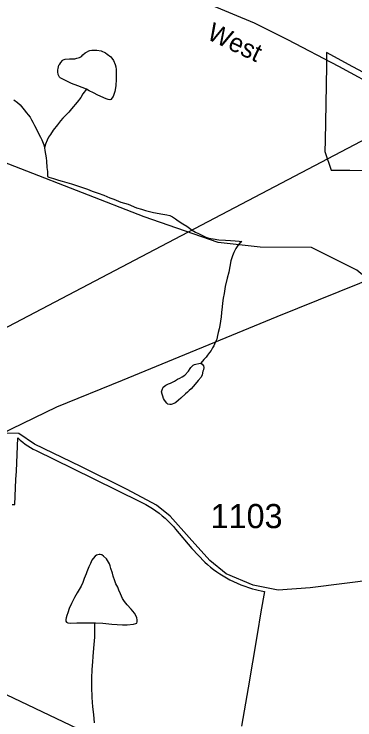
# Model space of a CAD drawing. Extents: x 2001466 to 2224147, y 644118 to 847247.
# Drawn here: x 2050483 to 2052246, y 663505 to 667157 of the extents above; entities that cross this region are included whole.
import ezdxf

# ---------------------------------------------------------------- set-up
doc = ezdxf.new("R2010")
doc.units = 0
for name, color, linetype in [('Exist Boundary Political City Limit New', 7, 'Continuous'), ('Exist Hydrographic Creek Single Shore', 7, 'Continuous'), ('Exist Hydrographic Misc Water Feature', 7, 'Continuous'), ('Exist Railroad Mainline', 7, 'Continuous'), ('Exist Road Primary NC Attributed', 7, 'Continuous'), ('Exist Road Secondary Type 51 Attributed', 7, 'Continuous'), ('Exist Road Secondary Type 51 Label', 7, 'Continuous'), ('Exist Road Secondary Type 51 Number Label', 7, 'Continuous'), ('Exist Utilities Electrical Transmission Line', 7, 'Continuous'), ('Map Preparation Boundary City Limit Buffer Line', 7, 'Continuous')]:
    doc.layers.add(name, color=color, linetype=linetype)

msp = doc.modelspace()

# ---------------------------------------------------------------- linework, layer by layer
at = {"layer": 'Exist Boundary Political City Limit New'}
for points in [[(2054801.8, 667751.5), (2053660.4, 667152.6), (2053327.5, 666977.9), (2052690.6, 666643.7), (2052574.2, 666699.1), (2052338.9, 666828.2), (2052265, 666867.9), (2052235.1, 666884), (2052099.1, 666957.6), (2052098.8, 666888.7), (2052095.1, 666691.8)], [(2052095.1, 666691.8), (2052092, 666502.8), (2052090.8, 666445.9), (2052123.5, 666350), (2052220.5, 666348.5), (2052394.6, 666345.8), (2052718.4, 666340.8), (2052814, 666339.7), (2052993.8, 666337.4), (2053061.5, 666128.9), (2053171.9, 666173.9), (2053238.5, 665962.8), (2053447.8, 666053.3), (2053459.1, 666013.7), (2054053.1, 666251.2), (2054374.5, 666381.3), (2054368.9, 666466.1), (2054832.8, 666624.4), (2055228.8, 666788.4), (2055490.1, 666895.9), (2055727.8, 666155.1)], [(2050474, 664618.4), (2050486.8, 664618.5), (2050493, 664748.4), (2050495, 664791.6), (2050503, 664963.4), (2050515.1, 664952.3), (2050527.8, 664941.8), (2050540.8, 664931.8), (2050554.2, 664922.4), (2050568.1, 664913.6), (2050582.4, 664905.4), (2050597, 664897.9), (2050787.6, 664804.9), (2050895.5, 664751.6), (2051136.9, 664633.8), (2051164.9, 664619.1), (2051182.5, 664608.8), (2051199.8, 664597.9), (2051216.5, 664586.4), (2051232.9, 664574.2), (2051248.8, 664561.4), (2051264.1, 664548.1), (2051279, 664534.2), (2051293.4, 664519.8), (2051307.2, 664504.8), (2051318.5, 664491.8), (2051403, 664392.1), (2051469.1, 664321.4), (2051484.1, 664308.1), (2051499.5, 664295.4), (2051515.2, 664283.1), (2051531.5, 664271.4), (2051548, 664260.1), (2051564.9, 664249.5), (2051582.1, 664239.4), (2051599.8, 664229.8), (2051617.6, 664220.8), (2051636.9, 664211.9), (2051656.5, 664203.7), (2051676.4, 664196.2), (2051696.6, 664189.3), (2051717, 664183.2), (2051731.4, 664179.2), (2051745.9, 664175.7), (2051760.6, 664172.5), (2051778, 664169.2), (2051760.1, 664063.8), (2051740.4, 663946.6), (2051716.2, 663803.9), (2051693.8, 663670.6), (2051660.2, 663472.7)]]:
    msp.add_lwpolyline(points, dxfattribs=at)
at = {"layer": 'Exist Hydrographic Creek Single Shore'}
msp.add_lwpolyline([(2053273.2, 665427.7), (2053006.3, 665420.1), (2052782.4, 665359), (2052490.4, 665574.9), (2052414.3, 665701.1), (2052256.4, 665832.3), (2052022.2, 665948.5), (2051756.3, 665950.7), (2051539.3, 665974.8), (2051155.3, 666107.3), (2050197.3, 666481), (2049997.3, 666488.4), (2049843.6, 666575.6)], dxfattribs=at)
at = {"layer": 'Exist Hydrographic Misc Water Feature'}
for points in [[(2050857.7, 666768), (2050813.6, 666786), (2050779.6, 666797.9), (2050739.6, 666817.7), (2050721.6, 666827.8), (2050717.7, 666829.8), (2050711.5, 666843.7), (2050709.7, 666857.7), (2050709.5, 666867.7), (2050711.5, 666875.7), (2050715.4, 666891.7), (2050719.5, 666897.8), (2050725.5, 666905.8), (2050733.5, 666915.8), (2050737.4, 666919.8), (2050741.5, 666921.8), (2050747.4, 666923.8), (2050769.4, 666925.8), (2050787.4, 666925.8), (2050797.2, 666925.9), (2050807.3, 666927.9), (2050821.4, 666931.9), (2050831.3, 666938), (2050839.3, 666945.9), (2050851.4, 666955.9), (2050857.3, 666959.9), (2050869.4, 666966), (2050875.4, 666968), (2050885.4, 666970), (2050911.3, 666970.1), (2050933.4, 666966.1), (2050955.3, 666956.1), (2050965.4, 666950.2), (2050983.4, 666936.2), (2050989.4, 666928.2), (2050997.4, 666916.3), (2051005.4, 666896.3), (2051009.5, 666884.3), (2051011.5, 666870.3), (2051011.5, 666852.3), (2051011.5, 666820.3), (2051009.7, 666786.3), (2051003.7, 666756.3), (2050995.7, 666730.3), (2050983.6, 666714.3), (2050977.7, 666712.3), (2050969.7, 666714.2), (2050959.6, 666718.2), (2050915.8, 666738.1), (2050893.6, 666750.1), (2050871.7, 666760), (2050857.7, 666768)], [(2050857.7, 666768), (2050839.7, 666744), (2050827.8, 666725.9), (2050809.8, 666701.9), (2050779.8, 666665.9), (2050765.9, 666649.9), (2050754, 666637.8), (2050735.9, 666617.8), (2050724, 666603.8), (2050708, 666583.8), (2050686.1, 666555.8), (2050672.2, 666533.7), (2050662.1, 666519.7), (2050654.1, 666503.7), (2050646.1, 666483.7), (2050640.2, 666465.6)], [(2050481.9, 666713.3), (2050501.8, 666699.4), (2050513.9, 666687.4), (2050536, 666661.4), (2050547.9, 666645.4), (2050555.9, 666635.4), (2050565.9, 666623.5), (2050573.9, 666609.5), (2050580.1, 666597.5), (2050588.1, 666579.6), (2050596.1, 666567.6), (2050610, 666539.6), (2050620.3, 666519.6), (2050626.2, 666505.6), (2050636.3, 666479.7), (2050640.2, 666465.6)], [(2050640.2, 666465.6), (2050642.2, 666451.7), (2050646.3, 666431.7), (2050648.4, 666413.7), (2050650.4, 666395.7), (2050652.5, 666363.7), (2050656.4, 666341.7), (2050656.6, 666315.7)], [(2050656.6, 666315.7), (2050662.5, 666313.8), (2050686.5, 666305.8), (2050712.6, 666297.8), (2050732.7, 666291.9), (2050780.6, 666277.9), (2050836.6, 666260.1), (2050862.7, 666250.2), (2050886.6, 666240.2), (2050918.6, 666230.2), (2050946.7, 666220.3), (2050978.7, 666206.3), (2050998.6, 666198.4), (2051034.7, 666184.4), (2051072.6, 666172.5), (2051116.7, 666154.6), (2051142.8, 666146.7), (2051162.6, 666140.7), (2051204.9, 666130.8), (2051252.9, 666120.9), (2051272.8, 666118.9), (2051288.8, 666115), (2051302.9, 666107), (2051318.9, 666097), (2051332.8, 666087), (2051356.8, 666071.1), (2051376.7, 666059.1), (2051390.9, 666049.2), (2051405, 666039.2), (2051421, 666029.2), (2051437, 666021.2), (2051474.9, 666003.3), (2051490.9, 665997.3), (2051512.9, 665993.4), (2051543, 665989.5), (2051576.9, 665987.5), (2051602.9, 665985.5), (2051626.9, 665983.6), (2051647, 665981.6), (2051660.9, 665979.6)], [(2051660.9, 665979.6), (2051650.9, 665971.6), (2051640.8, 665959.6), (2051631, 665943.6), (2051619.1, 665923.6), (2051613.1, 665905.6), (2051605.1, 665879.6), (2051599.2, 665851.6), (2051593.3, 665821.6), (2051585.3, 665789.6), (2051575.4, 665747.5), (2051569.5, 665711.5), (2051565.6, 665687.5), (2051561.5, 665661.6), (2051559.6, 665641.5), (2051555.7, 665613.5), (2051553.7, 665589.5), (2051551.6, 665567.5), (2051547.7, 665545.5), (2051543.8, 665527.6), (2051539.7, 665509.6), (2051535.8, 665493.5), (2051531.9, 665475.5), (2051523.9, 665457.5), (2051516, 665439.5), (2051510, 665429.5), (2051502, 665415.5), (2051494, 665405.5), (2051484, 665391.4), (2051476, 665381.4), (2051464.1, 665369.4), (2051449.7, 665351.4)], [(2051449.7, 665351.4), (2051456.1, 665345.4), (2051462.2, 665337.4), (2051464.1, 665327.4), (2051462.2, 665315.4), (2051460.2, 665309.4), (2051456.3, 665289.4), (2051450.3, 665277.4), (2051436.2, 665261.4), (2051420.2, 665241.3), (2051398.5, 665217.4), (2051388.4, 665209.3), (2051380.4, 665201.3), (2051370.4, 665191.3), (2051346.6, 665169.2), (2051334.5, 665159.2), (2051320.5, 665147.2), (2051314.6, 665143.1), (2051296.5, 665137.1), (2051288.5, 665137.1), (2051278.5, 665139.1), (2051272.6, 665143.1), (2051260.5, 665159.1), (2051256.6, 665167.1), (2051252.5, 665179), (2051248.4, 665191), (2051246.3, 665203), (2051248.4, 665213), (2051254.5, 665227), (2051268.5, 665237.1), (2051282.4, 665243.1), (2051292.2, 665247.1), (2051312.3, 665257.1), (2051328.3, 665267.1), (2051340.2, 665273.2), (2051352.3, 665279.2), (2051366.3, 665289.2), (2051386.2, 665309.3), (2051394.2, 665323.3), (2051398.3, 665327.3), (2051404.2, 665335.3), (2051410.1, 665339.4), (2051416.1, 665343.4), (2051424.1, 665345.4), (2051438.2, 665349.4), (2051449.7, 665351.4)], [(2050898.5, 664006.6), (2050904.7, 664006.6), (2050942.6, 664004.7), (2050988.6, 664000.8), (2051016.6, 663998.8), (2051044.5, 663996.9), (2051068.5, 663996.9), (2051100.7, 664000.9), (2051112.6, 664003), (2051118.6, 664005), (2051120.6, 664013), (2051120.6, 664021), (2051118.6, 664035), (2051106.5, 664057), (2051088.4, 664077), (2051068.5, 664100.9), (2051054.6, 664116.9), (2051044.3, 664132.8), (2051034.3, 664156.8), (2051024.4, 664176.8), (2051020.3, 664190.8), (2051010.3, 664208.8), (2051004.3, 664224.8), (2050996.3, 664248.8), (2050992, 664264.7), (2050984, 664288.7), (2050980.2, 664302.7), (2050976, 664312.7), (2050962.1, 664338.7), (2050946.1, 664352.7), (2050937.9, 664358.7), (2050928.1, 664360.6), (2050924, 664360.6), (2050910, 664356.6), (2050902, 664352.6), (2050892, 664340.5), (2050886.2, 664330.5), (2050878, 664314.5), (2050870, 664296.5), (2050860.2, 664270.5), (2050856.3, 664260.4), (2050846.3, 664236.4), (2050838.3, 664216.4), (2050830.5, 664196.5), (2050810.4, 664162.4), (2050796.4, 664138.4), (2050780.4, 664106.4), (2050768.5, 664080.3), (2050760.5, 664058.4), (2050756.6, 664044.3), (2050752.5, 664032.3), (2050750.7, 664024.3), (2050750.7, 664016.3), (2050754.8, 664010.3), (2050760.7, 664006.3), (2050774.7, 664004.4), (2050808.7, 664006.5), (2050836.6, 664006.5), (2050878.6, 664006.6), (2050898.5, 664006.6)], [(2050898.5, 664006.6), (2050898.7, 663968.6), (2050898.7, 663932.7), (2050894.8, 663876.6), (2050891, 663832.6), (2050888.9, 663804.7), (2050885.2, 663764.7), (2050883.2, 663720.6), (2050883.2, 663676.6), (2050885.4, 663620.7), (2050889.5, 663572.6), (2050893.4, 663532.7), (2050897.5, 663488.7)]]:
    msp.add_lwpolyline(points, dxfattribs=at)
at = {"layer": 'Exist Railroad Mainline'}
msp.add_lwpolyline([(2046464.5, 663426.2), (2046524.6, 663459.1), (2048551.7, 664535.4), (2049194.6, 664876.7), (2049524.4, 665051.8), (2049557.2, 665070.3), (2052622.8, 666680.7), (2055671.2, 668278.9), (2056997.6, 668963.3), (2058840.6, 669936.5)], dxfattribs=at)
at = {"layer": 'Exist Road Primary NC Attributed'}
msp.add_lwpolyline([(2050426, 664989), (2050469.1, 665011), (2050704.3, 665125.3), (2051044.1, 665262.3), (2051844.1, 665591.2), (2052698.6, 665937.8), (2053399.3, 666214.3), (2053976.4, 666455.2), (2054260.6, 666569.3)], dxfattribs=at)
at = {"layer": 'Exist Road Secondary Type 51 Attributed'}
for points in [[(2052557.1, 666646.2), (2052386.3, 666764), (2052162.5, 666885.4), (2051899.2, 667023.8), (2051726.1, 667110.4), (2051482.2, 667211.8), (2051238.9, 667288.9), (2050792.4, 667405.1), (2050170.2, 667573.1), (2049959.6, 667625.9), (2049883.6, 667635.4), (2049783.3, 667640.7), (2049542.6, 667618.5), (2049242.3, 667606.9)], [(2052683.1, 664272.6), (2052013.9, 664187.6), (2051850, 664175.9), (2051719.6, 664202.3), (2051580.5, 664260.9), (2051495.8, 664330.1), (2051388.7, 664448.4), (2051289.9, 664559.7), (2051219.6, 664615.4), (2051068.8, 664697.4), (2050828.7, 664816.1), (2050588.7, 664932.1), (2050508.7, 664986), (2050426, 664989)]]:
    msp.add_lwpolyline(points, dxfattribs=at)
at = {"layer": 'Exist Utilities Electrical Transmission Line'}
msp.add_lwpolyline([(2063583.7, 657590.1), (2059873.3, 658420.5), (2058009.5, 660180.5), (2056432.8, 660774), (2050997.3, 663369.7), (2049560.3, 664054.6)], dxfattribs=at)
at = {"layer": 'Map Preparation Boundary City Limit Buffer Line'}
for points in [[(2054801.8, 667751.5), (2053660.4, 667152.6), (2053327.5, 666977.9), (2052690.6, 666643.7), (2052574.2, 666699.1), (2052338.9, 666828.2), (2052265, 666867.9), (2052235.1, 666884), (2052099.1, 666957.6), (2052098.8, 666888.7), (2052095.1, 666691.8)], [(2052095.1, 666691.8), (2052092, 666502.8), (2052090.8, 666445.9), (2052123.5, 666350), (2052220.5, 666348.5), (2052394.6, 666345.8), (2052718.4, 666340.8), (2052814, 666339.7), (2052993.8, 666337.4), (2053061.5, 666128.9), (2053171.9, 666173.9), (2053238.5, 665962.8), (2053447.8, 666053.3), (2053459.1, 666013.7), (2054053.1, 666251.2), (2054374.5, 666381.3), (2054368.9, 666466.1), (2054832.8, 666624.4), (2055228.8, 666788.4), (2055490.1, 666895.9), (2055727.8, 666155.1)], [(2050474, 664618.4), (2050486.8, 664618.5), (2050493, 664748.4), (2050495, 664791.6), (2050503, 664963.4), (2050515.1, 664952.3), (2050527.8, 664941.8), (2050540.8, 664931.8), (2050554.2, 664922.4), (2050568.1, 664913.6), (2050582.4, 664905.4), (2050597, 664897.9), (2050787.6, 664804.9), (2050895.5, 664751.6), (2051136.9, 664633.8), (2051164.9, 664619.1), (2051182.5, 664608.8), (2051199.8, 664597.9), (2051216.5, 664586.4), (2051232.9, 664574.2), (2051248.8, 664561.4), (2051264.1, 664548.1), (2051279, 664534.2), (2051293.4, 664519.8), (2051307.2, 664504.8), (2051318.5, 664491.8), (2051403, 664392.1), (2051469.1, 664321.4), (2051484.1, 664308.1), (2051499.5, 664295.4), (2051515.2, 664283.1), (2051531.5, 664271.4), (2051548, 664260.1), (2051564.9, 664249.5), (2051582.1, 664239.4), (2051599.8, 664229.8), (2051617.6, 664220.8), (2051636.9, 664211.9), (2051656.5, 664203.7), (2051676.4, 664196.2), (2051696.6, 664189.3), (2051717, 664183.2), (2051731.4, 664179.2), (2051745.9, 664175.7), (2051760.6, 664172.5), (2051778, 664169.2), (2051760.1, 664063.8), (2051740.4, 663946.6), (2051716.2, 663803.9), (2051693.8, 663670.6), (2051660.2, 663472.7)]]:
    msp.add_lwpolyline(points, dxfattribs=at)

# ---------------------------------------------------------------- texts
at = {"layer": 'Exist Road Secondary Type 51 Label'}
msp.add_text('West', height=95, rotation=334.689, dxfattribs=at).set_placement((2051474.8, 667030.4))
at = {"layer": 'Exist Road Secondary Type 51 Number Label'}
msp.add_text('1103', height=125, dxfattribs=at).set_placement((2051499.9, 664496.9))

doc.saveas('drawing.dxf')
